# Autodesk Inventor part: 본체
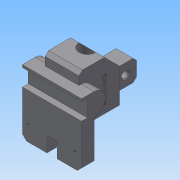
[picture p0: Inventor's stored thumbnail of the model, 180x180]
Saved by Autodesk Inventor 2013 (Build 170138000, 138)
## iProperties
Created: 2016-11
Part Number: 본체
Material: 일반
Document SubType Name: Modeling
Designer: Administrator
Density: 1 g/cm^3
Author: Administrator
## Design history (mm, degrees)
sketch "스케치3"
  geometry: L1 (24, 29)-(-24, 29); L2 (24, -29)-(24, 29); L3 (24, 29)-(-24, -29); L4 (-24, 29)-(24, -29); L5 (-24, 29)-(-24, -61); L6 (24, -29)-(-16, -29); L7 (-16, -29)-(-16, -61); L8 (-16, -61)-(-24, -61); 1 further point
  constraints: 16 end point, 2 midpoint, 2 parallel, 2 perpendicular, 1 horizontal
  dimensions: "d11" = 48 distance of L2.start L3.end; "d12" = 58 distance of L3.end L1.end; "d13" = 90 distance of L1.end L5.end; "d14" = 8 distance between parallel lines of L5 L7; "d15" = 58 distance between parallel lines of L1 L6; "d16" = 24 distance from line of L2 point (0, 0)
extrude "돌출2" new body sketch "스케치3" stored distance "d17" = 40; taper "d18" = 0 deg
sketch "스케치4"
  geometry: L1 (24, 29)-(24, -29) reference; L2 (24, -29)-(-16, -29) reference; L3 (-16, -29)-(-16, -61) reference; L4 (-16, -61)-(-24, -61) reference; L5 (-24, -61)-(-24, 29) reference; L6 (-24, 29)-(24, 29) reference; L7 (6, 29)-(24, 11); L8 (24, 29)-(6, 29); L9 (24, 28.074)-(24, 11); 1 further point
  constraints: 6 end point, 3 point on line
  dimensions: "d19" = 30 distance from line of L5 L7.start; "d21" = 45 deg angle of L7 L1
extrude "돌출3" cut sketch "스케치4" stored distance "d22" = 100; taper "d23" = 0 deg
chamfer "모따기1" distance "d24" = 4; stored, may be unused: second distance "d25" = 2, angle "d26" = 45 deg
node "작업 평면1"
sketch "스케치5"
  geometry: L1 (-16, -29)-(24, -29) reference; L2 (24, -29)-(24, 11) reference; L3 (24, 11)-(6, 29) reference; L4 (6, 29)-(-20, 29) reference; L5 (-24, -61)-(-16, -61) reference; L6 (-21, -61)-(-36, -61); L7 (-36, -61)-(-36, -8); L8 (-36, 2)-(-21, 2); L9 (-36, 12)-(-29, 12); L10 (-29, 12)-(-29, -8); L11 (-29, -8)-(-36, -8); L12 (-21, -11)-(-21, -61); L13 (-21, 15)-(-36, 15); L14 (-36, -8)-(-36, 2); L15 (-36, 12)-(-36, 15); A1 r 13 centre (-21, 2) between (-21, -11) and (-21, 15); 1 further point
  constraints: 20 end point, 7 perpendicular, 2 point on circle, 1 centre point, 1 coincident, 1 collinear, 1 point on line, 1 tangent
  dimensions: "d28" = 26 diameter of A1; "d35" = 63 distance of L6.end L8.start; "d36" = 15 distance of L8.start L8.end; "d38" = 10 distance from line of L11 A1.centre; "d39" = 10 distance from line of L9 A1.centre; "d40" = 7 distance between parallel lines of L7 L10; "d42" = 53 distance between parallel lines of L6 L11; "d105" = 60 distance between parallel lines of L7 L2; "d106" = 15 distance between parallel lines of L7 L12; "d107" = 15 distance of L13.start L13.end
extrude "돌출4" join sketch "스케치5" distance "d43" = 70; taper "d44" = 0 deg
sketch "스케치6"
  geometry: L1 (54, 1)-(24, 1); L2 (24, -24)-(54, -24); L3 (54, -24)-(54, 1); L4 (54, 1)-(25.939, -24); L5 (25.939, 1)-(54, -24); L6 (-36, -8)-(-36, -61) reference; L7 (-16, -29)-(24, -29) reference; L8 (-24, 25)-(-20, 29) reference; L9 (-20, 29)-(6, 29) reference; L10 (6, 29)-(24, 11) reference; L11 (24, 11)-(24, -29) reference; L12 (24, -29)-(-16, -29) reference; L13 (-16, -29)-(-16, -61) reference; L14 (-16, -61)-(-36, -61) reference; L15 (-36, -61)-(-36, -8) reference; L16 (-36, -8)-(-29, -8) reference; L17 (-29, -8)-(-29, 12) reference; L18 (-29, 12)-(-36, 12) reference; L19 (-36, 12)-(-36, 15) reference; L20 (-36, 15)-(-24, 15) reference; L21 (-24, 15)-(-24, 25) reference; 2 further points
  constraints: 10 end point, 4 point on line, 2 midpoint, 1 horizontal, 1 parallel
  dimensions: "d45" = 25 distance of L2.end L1.start; "d47" = 90 distance between parallel lines of L6 L3; "d48" = 5 distance between parallel lines of L2 L7
extrude "돌출5" join sketch "스케치6" stored distance "d49" = 20; taper "d50" = 0 deg
chamfer "모따기2" distance "d51" = 4; stored, may be unused: second distance "d52" = 2, angle "d53" = 45 deg
chamfer "모따기3" distance "d54" = 5; stored, may be unused: second distance "d55" = 2, angle "d56" = 45 deg
sketch "스케치7"
  geometry: L1 (40, 0)-(0, 0) reference; L2 (-10, -20)-(50, -20) reference; L3 (14, -6.373)-(14, -20); L4 (26, -6.373)-(26, -20); A1 r 29 centre (20, 22) between (1.106, 0) and (14, -6.373); A2 r 29 centre (20, 22) between (26, -6.373) and (38.894, 0); 1 further point
  constraints: 4 end point, 4 point on circle, 4 point on line, 2 centre point, 1 parallel, 1 perpendicular, 1 vertical alignment
  dimensions: "d59" = 42 distance from line of L2 A1.centre; "d60" = 6 distance from line of L4 A1.centre; "d61" = 6 distance from line of L3 A1.centre; "d62" = 29 radius of A2; "d63" = 29 radius of A1
extrude "돌출6" cut sketch "스케치7" distance "d64" = 18; taper "d65" = 0 deg
sketch "스케치8"
  geometry: L1 (26, -60)-(50, -60) reference; 2 further points
  constraints: 1 vertical alignment
  dimensions: "d68" = 42 distance from line of L1 point (20, -18)
hole "구멍1" sketch "스케치8" at (20, -18) diameter "d69" = 20; stored, may be unused: countersink angle "d73" = 90 deg, drill point angle "d75" = 0 deg; dims "d70" = 6, "d71" = 29, "d72" = 7, "d74" = 8
sketch "스케치9"
  geometry: L1 (-1, 50)-(-1, 24) reference; L2 (8, -36)-(56, -36) reference; C1 r 4 at (11.5, 41); 2 further points
  constraints: 1 centre point
  dimensions: "d76" = 8 diameter of C1; "d77" = 12.5 distance from line of L1 C1.centre; "d78" = 77 distance from line of L2 C1.centre
extrude "돌출7" cut sketch "스케치9" stored distance "d79" = 10; taper "d80" = 0 deg
sketch "스케치10"
  geometry: L1 (29, -16)-(29, 24) reference; L2 (29, 24)-(-11, 24) reference; 2 further points
  constraints: 1 other
  dimensions: "d81" = 25 distance from line of L1 point (4, 6); "d82" = 18 distance from line of L2 point (4, 6)
feature "엠보싱1" sketch "스케치10" dims "d11" = 48, "d12" = 58, "d13" = 90, "d14" = 8, "d15" = 58, "d16" = 24, "d83" = 0.5, "d84" = 0
fillet "모깎기3" dims "d100" = 3
chamfer "모따기4" distance "d101" = 1; stored, may be unused: second distance "d102" = 2, angle "d103" = 45 deg
sketch "스케치12"
  geometry: L1 (24, 0)-(0, 0) reference; L2 (60, 0)-(36, 0) reference; 3 further points
  dimensions: "d109" = 27.5 horizontal distance of point (30, -61) point (2.5, -18); "d110" = 27.5 horizontal distance of point (57.5, -18) point (30, -61); "d111" = 18 distance from line of point (2.5, -18) L1; "d112" = 18 distance from line of point (57.5, -18) L2
hole "구멍3" sketch "스케치12" at (2.5, -18), (57.5, -18) diameter "d113" = 3.242; stored, may be unused: countersink angle "d117" = 90 deg, drill point angle "d119" = 118 deg; dims "d114" = 6, "d115" = 4, "d116" = 2, "d118" = 8
fillet "모깎기5" dims "d120" = 3
fillet "모깎기6" dims "d121" = 5
node "솔리드2"
node "절단 모서리 투영1"
node "절단 모서리 투영2"
other parameters: "d27" = 35, "d57" = 58
